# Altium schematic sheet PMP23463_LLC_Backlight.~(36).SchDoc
size 431 x 279 mm; Date: Not shown in title block; ApprovedBy: Not shown in title block; CheckedBy: Not shown in title block; Author: Not shown in title block; CompanyName: Not shown in title block; Engineer: Not shown in title block; Organization: Not shown in title block; Address1: Not shown in title block; Address2: Not shown in title block; Address3: Not shown in title block; Address4: Not shown in title block; DocumentNumber: 2; Revision: Use project parameter SCH_Rev; SheetNumber: 1; SheetTotal: 1; PageSetup: Record=PageOptions¦CenterHorizontal=True¦CenterVertical=True¦PrintScale=1.00¦XCorrection=1.00¦YCorrection=1.00¦PrintKind=0¦BorderSize=5000000¦LeftOffset=0¦BottomOffset=0¦Orientation=2¦PaperLength=1000¦PaperWidth=1000¦Scale=100¦PaperSource=15¦PrintQuality=600¦MediaType=1¦DitherType=10¦PaperKind=Letter¦PrintScaleMode=1
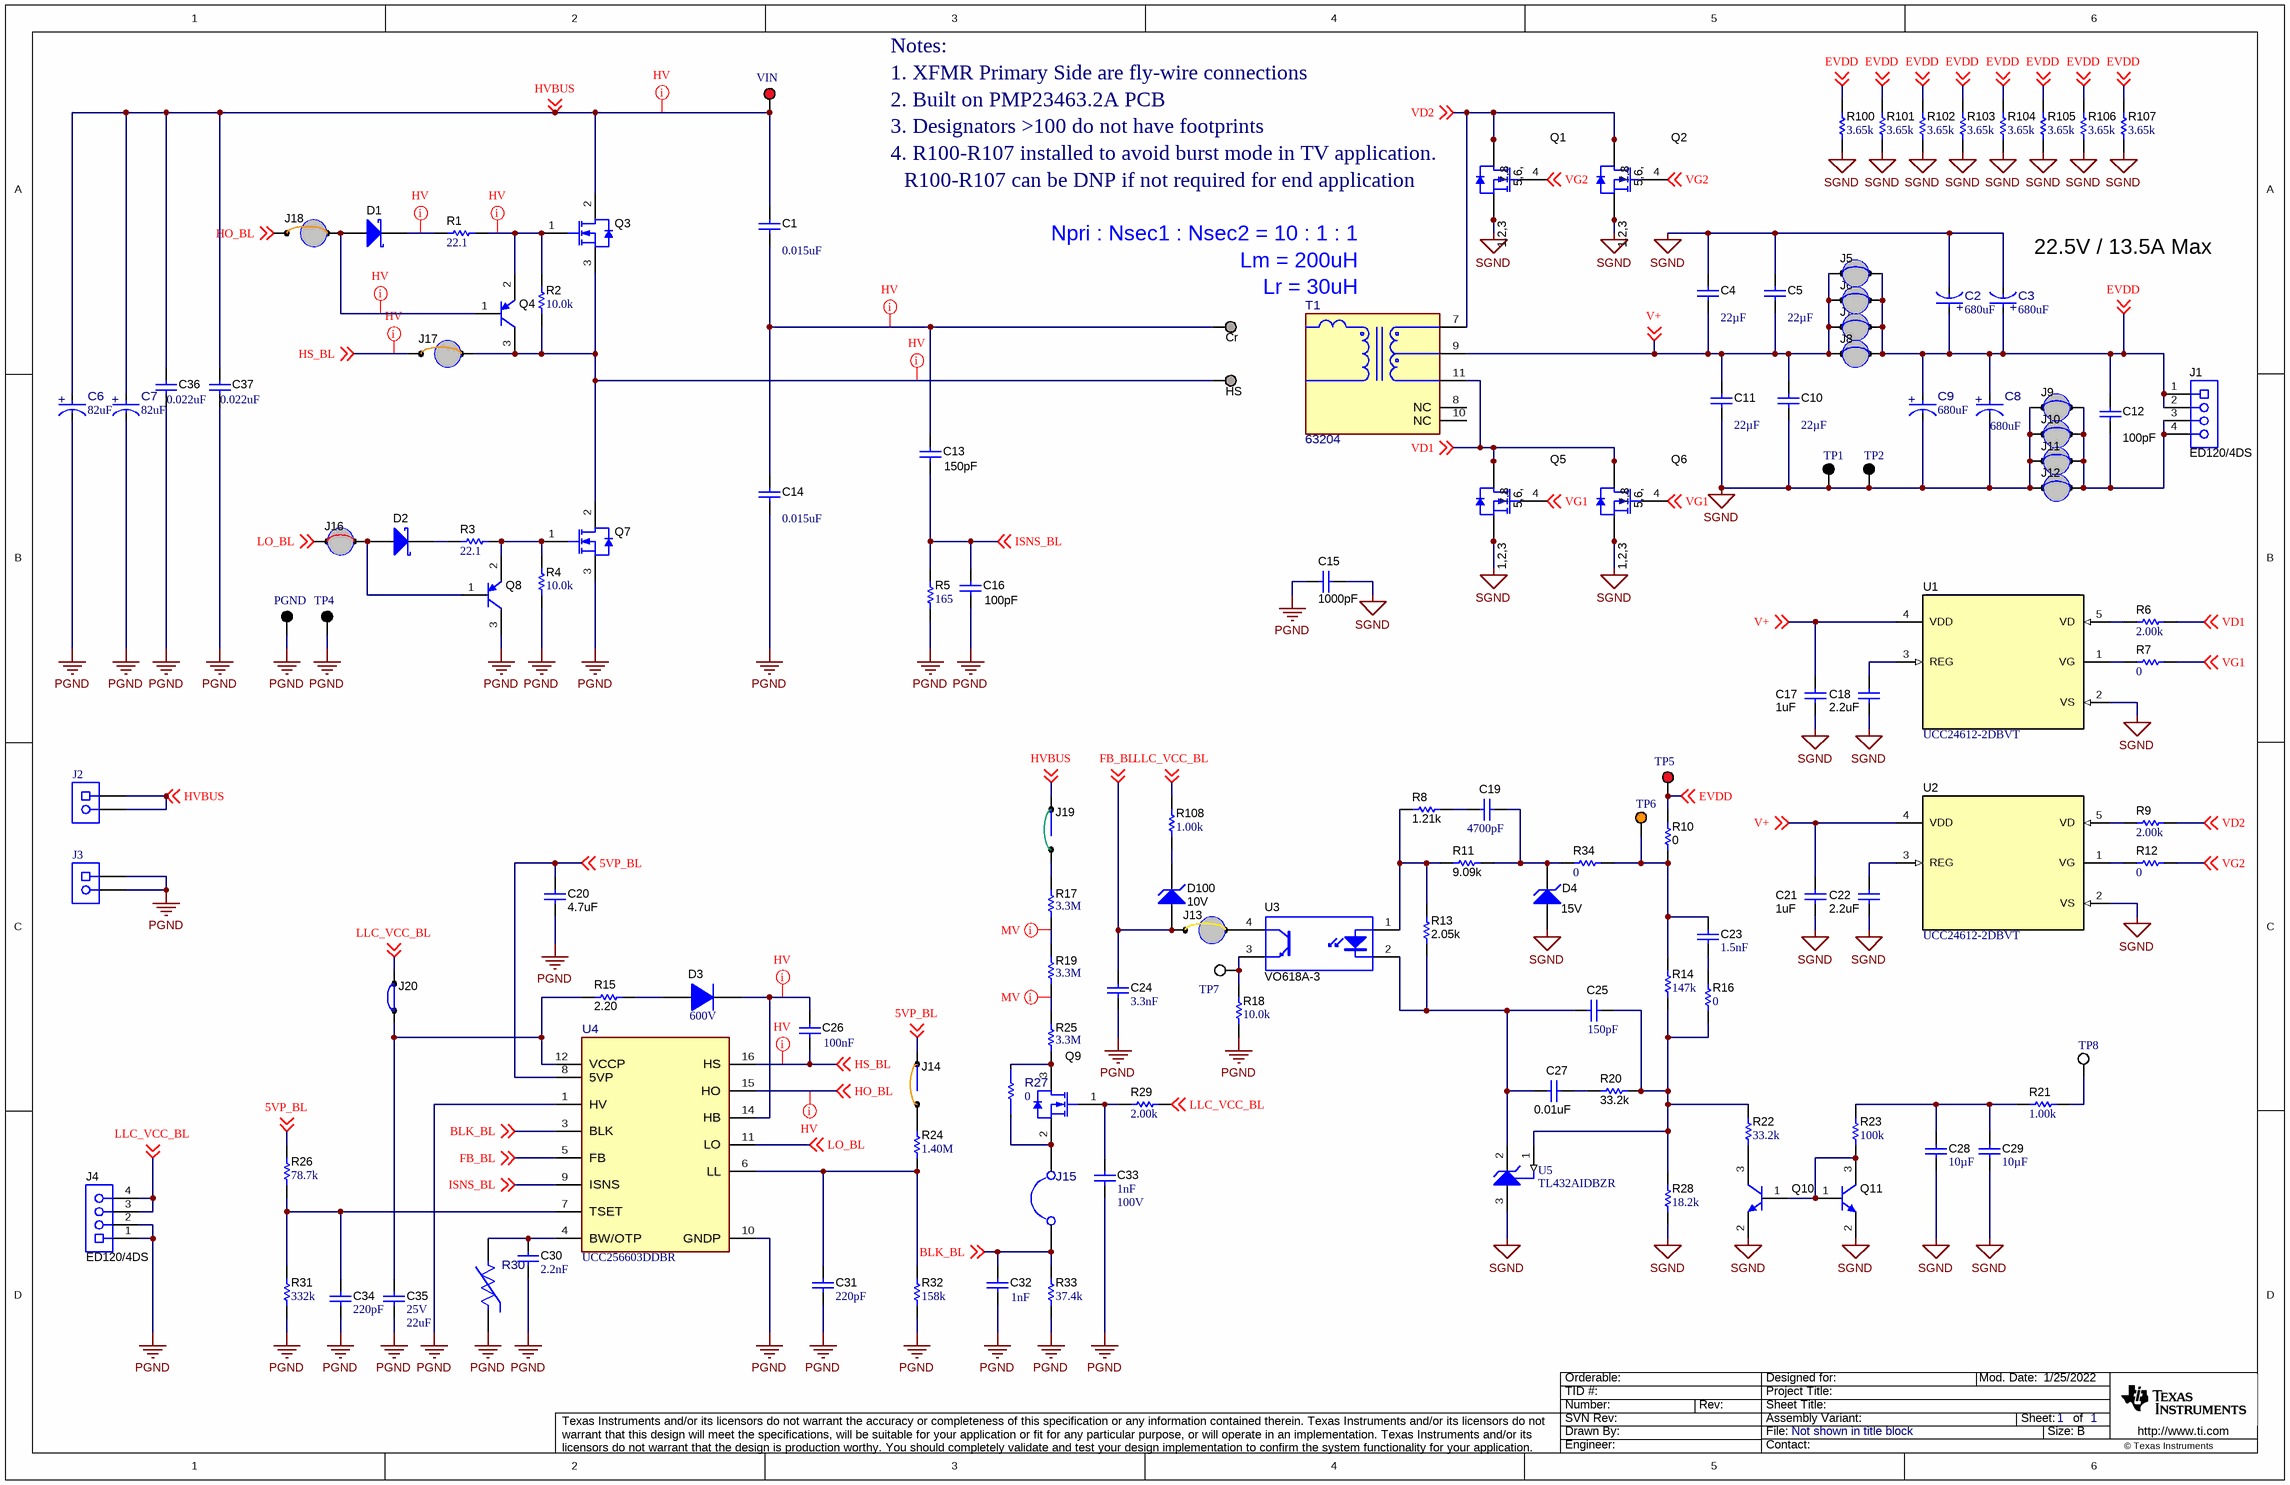
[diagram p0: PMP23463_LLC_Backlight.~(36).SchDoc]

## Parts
C1  ValueDisplayed: 0.015uF  [PHE426_1300x400x900]  (hidden comment: PHE426MA5150JR05)
C2  ValueDisplayed: 680uF  [FP-EKZM350ELL681MJ25S_horizontalUp-MFG]  (hidden comment: EKZM350ELL681MJ25S)
C3  ValueDisplayed: 680uF  [FP-EKZM350ELL681MJ25S_horizontalUp-MFG]  (hidden comment: EKZM350ELL681MJ25S)
C4  ValueDisplayed: 22µF  [1210]  (hidden comment: GMK325BJ226MM-P)
C5  ValueDisplayed: 22µF  [1210]  (hidden comment: GMK325BJ226MM-P)
C6  ValueDisplayed: 82uF  [FP-450HXW82MEFR10X60_horizontalUp]  (hidden comment: 450HXW82MEFR10X60)
C7  ValueDisplayed: 82uF  [FP-450HXW82MEFR10X60_horizontalUp]  (hidden comment: 450HXW82MEFR10X60)
C8  ValueDisplayed: 680uF  [FP-EKZM350ELL681MJ25S_horizontalUp-MFG]  (hidden comment: EKZM350ELL681MJ25S)
C9  ValueDisplayed: 680uF  [FP-EKZM350ELL681MJ25S_horizontalUp-MFG]  (hidden comment: EKZM350ELL681MJ25S)
C10  ValueDisplayed: 22µF  [1210]  (hidden comment: GMK325BJ226MM-P)
C11  ValueDisplayed: 22µF  [1210]  (hidden comment: GMK325BJ226MM-P)
C12  ValueDisplayed: 100pF  [0603L]  (hidden comment: 06035A101FAT2A)
C13  ValueDisplayed: 150pF  [1206L]  (hidden comment: GRM31A5C2J151JW01D)
C14  ValueDisplayed: 0.015uF  [PHE426_1300x400x900]  (hidden comment: PHE426MA5150JR05)
C15  ValueDisplayed: 1000pF  [CD45_700x600x1100]  (hidden comment: CD45-E2GA102M-NKA)
C16  ValueDisplayed: 100pF  [1206L]  (hidden comment: 12061A101JAT2A)
C17  ValueDisplayed: 1uF  [0603L]  (hidden comment: GRM188R71C105KE15D)
C18  ValueDisplayed: 2.2uF  [0805L]  (hidden comment: C2012X7R1V225K085AC)
C19  ValueDisplayed: 4700pF  [0603L]  (hidden comment: C0603C472J1GAC7867)
C20  ValueDisplayed: 4.7uF  [1206L]  (hidden comment: C3216X7R1E475K085AB)
C21  ValueDisplayed: 1uF  [0603L]  (hidden comment: GRM188R71C105KE15D)
C22  ValueDisplayed: 2.2uF  [0805L]  (hidden comment: C2012X7R1V225K085AC)
C23  Cap_F: 1.5nF  [0603]  (hidden comment: C0603C152K5RACTU)
C24  Cap_F: 3.3nF  [0603]  (hidden comment: C0603C332K5RACTU)
C25  ValueDisplayed: 150pF  [0603]  (hidden comment: 06035A151JAT2A)
C26  Cap_F: 100nF  [1206_180L]  (hidden comment: GRM31C5C1E104JA01L)
C27  ValueDisplayed: 0.01uF  [0603L]  (hidden comment: 06031C103JAT2A)
C28  ValueDisplayed: 10µF  [1206_180]  (hidden comment: C1206C106J3RACAUTO)
C29  ValueDisplayed: 10µF  [1206_180]  (hidden comment: C1206C106J3RACAUTO)
C30  Cap_F: 2.2nF  [0603]  (hidden comment: C0603X222K5RACTU)
C31  Cap_F: 220pF  [0603]  (hidden comment: C0603X221K5RACTU)
C32  Cap_F: 1nF  [0402L]  (hidden comment: 04025C102JAT2A)
C33  Cap_F: 1nF  VDC_V: 100V  [0603]  (hidden comment: C1608X7R2A102K080AA)
C34  Cap_F: 220pF  [0603]  (hidden comment: C0603X221K5RACTU)
C35  VDC_V: 25V  ValueDisplayed: 22uF  [1206_190]  (hidden comment: TMK316BBJ226ML-T)
C36  ValueDisplayed: 0.022uF  [1210_150]  (hidden comment: GRM32QR72J223KW01L)
C37  ValueDisplayed: 0.022uF  [1210_150]  (hidden comment: GRM32QR72J223KW01L)
Cr  0312-0-15-15-34-27-10-0  [Mill-Max_0312-0-15-15-34-27-10-0]  (value not drawn)
D1  PMEG3010EGWJ  [SOD-123]  (value not drawn)
D2  PMEG3010EGWJ  [SOD-123]  (value not drawn)
D3  Vr_V: 600V  [SMAF]  (hidden comment: ES1JAF)
D4  value 15V  [SOD-323]  (hidden comment: MM3Z15VST1G)
D100  value 10V  [SOD-523]  (hidden comment: BZT52C10T-7)
HS  0312-0-15-15-34-27-10-0  [Mill-Max_0312-0-15-15-34-27-10-0]  (value not drawn)
J1  ED120/4DS  [On-Shore_ED120_4DS]
J2  Receptacle_2x1  [On-Shore_ED120_2DS]  (value not drawn)
J3  Receptacle_2x1  [On-Shore_ED120_2DS]  (value not drawn)
J4  ED120/4DS  [On-Shore_ED120_4DS]
J5  923345-06-C  [CONN_923345-06-C]  (value not drawn)
J6  923345-06-C  [CONN_923345-06-C]  (value not drawn)
J7  923345-06-C  [CONN_923345-06-C]  (value not drawn)
J8  923345-06-C  [CONN_923345-06-C]  (value not drawn)
J9  923345-06-C  [CONN_923345-06-C]  (value not drawn)
J10  923345-06-C  [CONN_923345-06-C]  (value not drawn)
J11  923345-06-C  [CONN_923345-06-C]  (value not drawn)
J12  923345-06-C  [CONN_923345-06-C]  (value not drawn)
J13  923345-04-C  [3M_923345-04-C]  (value not drawn)
J14  923345-03-C  [923345-03-C]  (value not drawn)
J15  923345-10-C  [FP-923345-10-C_JUMPER2-MFG]  (value not drawn)
J16  923345-02-C  [923345-02-C]  (value not drawn)
J17  923345-03-C  [923345-03-C]  (value not drawn)
J18  923345-03-C  [923345-03-C]  (value not drawn)
J19  923345-05-C  [923345-05-C]  (value not drawn)
J20  923345-06-C  [CONN_923345-06-C]  (value not drawn)
PGND  5011  [Keystone5011]  (value not drawn)
Q1  BSC052N08NS5ATMA1  [PG-TDSON-8]  (value not drawn)
Q2  BSC052N08NS5ATMA1  [PG-TDSON-8]  (value not drawn)
Q3  IPP60R099C7XKSA1  [TO-220AB_Horizontal_100mil_Standoff2300]  (value not drawn)
Q4  BC858C-7-F  [SOT-23]  (value not drawn)
Q5  BSC052N08NS5ATMA1  [PG-TDSON-8]  (value not drawn)
Q6  BSC052N08NS5ATMA1  [PG-TDSON-8]  (value not drawn)
Q7  IPP60R099C7XKSA1  [TO-220AB_Horizontal_100mil_Standoff2300]  (value not drawn)
Q8  BC858C-7-F  [SOT-23]  (value not drawn)
Q9  BSS127S-7  [SOT-23]  (value not drawn)
Q10  MMBTA05LT1G  [SOT-23]  (value not drawn)
Q11  MMBTA05LT1G  [SOT-23]  (value not drawn)
R1  ValueDisplayed: 22.1  [0603]  (hidden comment: RC0603FR-0722R1L)
R2  ValueDisplayed: 10.0k  [1206]  (hidden comment: CRCW120610K0FKEA)
R3  ValueDisplayed: 22.1  [0603]  (hidden comment: RC0603FR-0722R1L)
R4  ValueDisplayed: 10.0k  [0603]  (hidden comment: M55342K12B10E0T)
R5  ValueDisplayed: 165  [1206]  (hidden comment: RC1206FR-07165RL)
R6  ValueDisplayed: 2.00k  [0603]  (hidden comment: RC0603FR-072KL)
R7  ValueDisplayed: 0  [0603L]  (hidden comment: RC0603JR-070RL)
R8  ValueDisplayed: 1.21k  [0603L]  (hidden comment: RC0603FR-071K21L)
R9  ValueDisplayed: 2.00k  [0603]  (hidden comment: RC0603FR-072KL)
R10  ValueDisplayed: 0  [0402L]  (hidden comment: RC0402JR-070RL)
R11  ValueDisplayed: 9.09k  [0603L]  (hidden comment: RC0603FR-079K09L)
R12  ValueDisplayed: 0  [0805_HV]  (hidden comment: RC0805JR-070RL)
R13  ValueDisplayed: 2.05k  [0603L]  (hidden comment: RC0603FR-072K05L)
R14  ValueDisplayed: 147k  [0603L]  (hidden comment: RC0603FR-07147KL)
R15  ValueDisplayed: 2.20  [0603L]  (hidden comment: ERJ-3RQF2R2V)
R16  ValueDisplayed: 0  [0603]  (hidden comment: RMCF0603ZT0R00)
R17  Res_ohm: 3.3M  [FP-KTR18EZPF3304_1206-MFG]  (hidden comment: KTR18EZPF3304)
R18  ValueDisplayed: 10.0k  [0402L]  (hidden comment: ERJ-2RKF1002X)
R19  Res_ohm: 3.3M  [FP-KTR18EZPF3304_1206-MFG]  (hidden comment: KTR18EZPF3304)
R20  ValueDisplayed: 33.2k  [0603L]  (hidden comment: RC0603FR-0733K2L)
R21  ValueDisplayed: 1.00k  [0603L]  (hidden comment: CRCW06031K00FKEA)
R22  ValueDisplayed: 33.2k  [0603]  (hidden comment: RC0603FR-0733K2L)
R23  ValueDisplayed: 100k  [0603]  (hidden comment: RC0603FR-07100KL)
R24  ValueDisplayed: 1.40M  [1206]  (hidden comment: RC1206FR-071M4L)
R25  Res_ohm: 3.3M  [FP-KTR18EZPF3304_1206-MFG]  (hidden comment: KTR18EZPF3304)
R26  ValueDisplayed: 78.7k  [0603]  (hidden comment: RC0603FR-0778K7L)
R27  value 0  [FP-RMCF1206ZT0R00_1206-MFG]  (hidden comment: RMCF1206ZT0R00)
R28  ValueDisplayed: 18.2k  [0603]  (hidden comment: RC0603FR-0718K2L)
R29  ValueDisplayed: 2.00k  [0603]  (hidden comment: RC0603FR-072KL)
R30  B57371V2474J060  [FP-B57371V2474J060_0603-MFG]  (value not drawn)
R31  ValueDisplayed: 332k  [0603]  (hidden comment: RC0603FR-07332KL)
R32  ValueDisplayed: 158k  [0603]  (hidden comment: RC0603FR-07158KL)
R33  ValueDisplayed: 37.4k  [0603]  (hidden comment: RC0603FR-0737K4L)
R34  ValueDisplayed: 0  [0603]  (hidden comment: RMCF0603ZT0R00)
R100  ValueDisplayed: 3.65k  [1206]  (hidden comment: RC1206FR-073K65L)
R101  ValueDisplayed: 3.65k  [1206]  (hidden comment: RC1206FR-073K65L)
R102  ValueDisplayed: 3.65k  [1206]  (hidden comment: RC1206FR-073K65L)
R103  ValueDisplayed: 3.65k  [1206]  (hidden comment: RC1206FR-073K65L)
R104  ValueDisplayed: 3.65k  [1206]  (hidden comment: RC1206FR-073K65L)
R105  ValueDisplayed: 3.65k  [1206]  (hidden comment: RC1206FR-073K65L)
R106  ValueDisplayed: 3.65k  [1206]  (hidden comment: RC1206FR-073K65L)
R107  ValueDisplayed: 3.65k  [1206]  (hidden comment: RC1206FR-073K65L)
R108  ValueDisplayed: 1.00k  [0603]  (hidden comment: ERJ-3EKF1001V)
T1  63204  [FP-63204_PTH_XRMS_80MM0_64MM0-MFG]
TP1  5011  [Keystone5011]  (value not drawn)
TP2  5011  [Keystone5011]  (value not drawn)
TP4  5011  [Keystone5011]  (value not drawn)
TP5  5010  [Keystone5010]  (value not drawn)
TP6  5013  [Keystone5013]  (value not drawn)
TP7  5012  [Keystone5012]  (value not drawn)
TP8  5012  [Keystone5012]  (value not drawn)
U1  UCC24612-2DBVT  [DBV0005A_N]
U2  UCC24612-2DBVT  [DBV0005A_N]
U3  VO618A-3  [DIP-4]
U4  UCC256603DDBR  [DDB0014A-MFG]
U5  TL432AIDBZR  [DBZ0003A_N]
VIN  5010  [Keystone5010]  (value not drawn)

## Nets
PGND: C6.1(CATHODE) C7.1(CATHODE) C14.2 C15.2 C16.2 C20.2 C24.2 C30.2 C31.2 C32.2 C33.2 C34.2 C35.2 C36.2 C37.2 J3.1 J3.2 J4.1 J4.2 PGND.1 Q7.3(S) Q8.3(C) R4.1 R5.1 R18.1 R30.1 R31.1 R32.1 R33.1 TP4.1 U4.1(HV) U4.10(GNDP)
SGND: C2.1(CATHODE) C3.1(CATHODE) C4.1 C5.1 C8.1(CATHODE) C9.1(CATHODE) C10.2 C11.2 C15.1 C17.2 C18.2 C21.2 C22.2 C28.2 C29.2 D4.2(A) J9.1 J10.1 J11.1 J12.1 Q1.1(S) Q1.2(S) Q1.3(S) Q2.1(S) Q2.2(S) Q2.3(S) Q5.1(S) Q5.2(S) Q5.3(S) Q6.1(S) Q6.2(S) Q6.3(S) Q10.2(E) Q11.2(E) R28.1 R100.1 R101.1 R102.1 R103.1 R104.1 R105.1 R106.1 R107.1 TP1.1 TP2.1 U1.2(VS) U2.2(VS) U5.3(ANODE)
5VP_BL: C20.1 J14.2 R26.2 U4.8(5VP) ; off-sheet 5VP_BL
BLK_BL: C32.1 J15.1 R33.2 U4.3(BLK) ; off-sheet BLK_BL
EVDD: C2.2(ANODE) C3.2(ANODE) C8.2(ANODE) C9.2(ANODE) C12.1 J1.1 J1.2 J5.2 J6.2 J7.2 J8.2 R10.2 R100.2 R101.2 R102.2 R103.2 R104.2 R105.2 R106.2 R107.2 TP5.1 ; off-sheet EVDD
FB_BL: C24.1 D100.2(A) J13.1 U4.5(FB) ; off-sheet FB_BL
HO_BL: J18.1 U4.15(HO) ; off-sheet HO_BL
HS_BL: C26.2 J17.1 U4.16(HS) ; off-sheet HS_BL
HVBUS: C1.1 C6.2(ANODE) C7.2(ANODE) C36.1 C37.1 J2.1 J2.2 J19.2 Q3.2(D) VIN.1 ; off-sheet HVBUS
ISNS_BL: C13.2 C16.1 R5.2 U4.9(ISNS) ; off-sheet ISNS_BL
LLC_VCC_BL: J4.3 J4.4 J20.2 R29.2 R108.2 ; off-sheet LLC_VCC_BL
LO_BL: J16.1 U4.11(LO) ; off-sheet LO_BL
V+: C4.2 C5.2 C10.1 C11.1 C17.1 C21.1 J5.1 J6.1 J7.1 J8.1 T1.9 U1.4(VDD) U2.4(VDD) ; off-sheet V+
VD1: Q5.5(D) Q5.6(D) Q5.7(D) Q5.8(D) Q5.9(D) Q6.5(D) Q6.6(D) Q6.7(D) Q6.8(D) Q6.9(D) R6.2 T1.11 ; off-sheet VD1
VD2: Q1.5(D) Q1.6(D) Q1.7(D) Q1.8(D) Q1.9(D) Q2.5(D) Q2.6(D) Q2.7(D) Q2.8(D) Q2.9(D) R9.2 T1.7 ; off-sheet VD2
VG1: Q5.4(G) Q6.4(G) R7.1 ; off-sheet VG1
VG2: Q1.4(G) Q2.4(G) R12.2 ; off-sheet VG2
NetC1_2: C1.2 C13.1 C14.1 Cr.1
NetC12_2: C12.2 J1.3 J1.4 J9.2 J10.2 J11.2 J12.2
NetC18_1: C18.1 U1.3(REG)
NetC19_1: C19.1 D4.1(K) R11.2 R34.1
NetC19_2: C19.2 R8.2
NetC22_1: C22.1 U2.3(REG)
NetC23_1: C23.1 R10.1 R14.2 R34.2 TP6.1
NetC23_2: C23.2 R16.2
NetC25_1: C25.1 R14.1 R16.1 R20.1 R22.2 R28.2 U5.1(REF)
NetC25_2: C25.2 C27.2 R13.1 U3.2(K) U5.2(CATHODE)
NetC26_1: C26.1 D3.1(K) U4.14(HB)
NetC27_1: C27.1 R20.2
NetC28_1: C28.1 C29.1 R21.1 R23.2
NetC30_1: C30.1 R30.2 U4.4(BW/OTP)
NetC31_1: C31.1 R24.1 R32.2 U4.6(LL)
NetC33_1: C33.1 Q9.1(G) R29.1
NetC34_1: C34.1 R26.1 R31.2 U4.7(TSET)
NetC35_1: C35.1 J20.1 R15.1 U4.12(VCCP)
NetD1_1: D1.1(K) R1.1
NetD1_2: D1.2(A) J18.2 Q4.1(B)
NetD2_1: D2.1(K) R3.1
NetD2_2: D2.2(A) J16.2 Q8.1(B)
NetD3_2: D3.2(A) R15.2
NetD100_1: D100.1(K) R108.1
NetHS_1: HS.1 J17.2 Q3.3(S) Q4.3(C) Q7.2(D) R2.1
NetJ13_2: J13.2 U3.4(C)
NetJ14_1: J14.1 R24.2
NetJ15_2: J15.2 Q9.2(S) R27.1
NetJ19_1: J19.1 R17.2
NetQ3_1: Q3.1(G) Q4.2(E) R1.2 R2.2
NetQ7_1: Q7.1(G) Q8.2(E) R3.2 R4.2
NetQ9_3: Q9.3(D) R25.1 R27.2
NetQ10_1: Q10.1(B) Q11.1(B) Q11.3(C) R23.1
NetQ10_3: Q10.3(C) R22.1
NetR6_1: R6.1 U1.5(VD)
NetR7_2: R7.2 U1.1(VG)
NetR8_1: R8.1 R11.1 R13.2 U3.1(A)
NetR9_1: R9.1 U2.5(VD)
NetR12_1: R12.1 U2.1(VG)
NetR17_1: R17.1 R19.2
NetR18_2: R18.2 TP7.1 U3.3(E)
NetR19_1: R19.1 R25.2
NetR21_2: R21.2 TP8.1

Not connected (* = marked no-connect by the designer): T1 8(NC) 10(NC)

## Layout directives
net class HV: HO_BL, HS_BL, HVBUS, NetC1_2, NetC26_1, NetD1_1, NetD1_2, NetHS_1, NetQ3_1
net class MV: NetR17_1, NetR19_1

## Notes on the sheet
- Notes:
- 1. XFMR Primary Side are fly-wire connections
- 2. Built on PMP23463.2A PCB
- 3. Designators >100 do not have footprints
- (near Q1) 4. R100-R107 installed to avoid burst mode in TV application.
- (near Q1) R100-R107 can be DNP if not required for end application
- Npri : Nsec1 : Nsec2 = 10 : 1 : 1
- Lm = 200uH
- (near Cr) Lr = 30uH
- (near C3) 22.5V / 13.5A Max

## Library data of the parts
C1 C14 = CMP-0012541-3: CAP, Film, 0.015 uF, 630 V, +/- 20%, TH; Manufacturer: Kemet; TaMin_C: -55°C; Polarized: N; SizeAreaWB_mm2: 90; Value1: Unknown; TaMax_C: 105°C; SizeZ_mm: 9; SizeX_mm: 13; SizeY_mm: 4; Cap_Case: 13x4x9mm; Value2: 630V; SizeArea_mm2: 52; Cap_F: 15nF; AEC Category: Q200
C2 C3 C8 C9 = CMP-0001423-2: Cap Aluminum Lytic 680uF 35V 20% (10 X 25mm) Radial 5mm 2250mA 10000h 105 Bulk; Manufacturer: United Chemi-Con; AEC Qualified: No; Cap_F: 680µF; IRMS_A: 2.25A; SizeZ_mm: 26.5mm; Dissipation Factor: 12%; Leakage Current: 238uA; Life: 10000Hours; Value: 680µF
C4 C5 C10 C11 = CMP-0085817-1: CAP, CERM, 22 µF, 35 V,+/- 20%, X5R, 1210; Manufacturer: Taiyo Yuden; Value: 22uF; VDC_V: 35V; SizeZ_mm: 1.35; TaMax_C: 85°C; U/M: EA; SizeAreaWB_mm2: 14.7; SizeX_mm: 3.2; SizeArea_mm2: 8; TaMin_C: -55°C; AEC Qualified: N; SizeY_mm: 2.5; AEC Category: Q200
C6 C7 = CMP-0120349-2: 82 µF 450 V Aluminum Electrolytic Capacitors Radial, Can 2000 Hrs @ 105°C; Manufacturer: Rubycon; AEC Qualified: No; Cap_F: 82µF; IRMS_A: 710mA; SizeZ_mm: 62mm; Tolerance_%: 20%; VDC_V: 450V; Dissipation Factor: 25%; Leakage Current: 576.28uA; Life: 2000Hours; Value: 82µF
C12 = CMP-0006762-4: CAP, CERM, 100 pF, 50 V, +/- 1%, C0G/NP0, 0603; Manufacturer: AVX; TaMin_C: -55°C; Polarized: N; SizeAreaWB_mm2: 4.68; Value1: Unknown; U/M: EA; TaMax_C: 125°C; SizeZ_mm: 1; SizeX_mm: 1.6; SizeY_mm: 0.8; Cap_Case: 0603; Value2: 50V; SizeArea_mm2: 1.28; CompType: Capacitor; Value: 100pF; AEC Category: Q200
C13 = CMP-0008885-2: CAP, CERM, 150 pF, 630 V, +/- 5%, C0G/NP0, 1206; Manufacturer: MuRata; TaMin_C: -55°C; Polarized: N; SizeAreaWB_mm2: 10.92; Value1: Unknown; U/M: EA; Value: 150pF; TaMax_C: 125°C; SizeZ_mm: 1.35; SizeX_mm: 3.2; SizeY_mm: 1.6; Cap_Case: 1206; Value2: 630V; SizeArea_mm2: 5.12; CompType: Capacitor; AEC Category: Q200
C15 = CMP-0009595-2: CAP, CERM, 1000 pF,  V, +/- 20%, E, D7xT6mm; Manufacturer: TDK; TaMin_C: -25°C; Polarized: N; SizeAreaWB_mm2: 101.2; Value1: Unknown; U/M: EA; Value: 1000pF; TaMax_C: 125°C; SizeZ_mm: 11; SizeX_mm: 10.65; SizeY_mm: 6; Cap_Case: 7x6x11mm; SizeArea_mm2: 63.9; Cap_F: 1nF; AEC Category: Q200
C16 = CMP-0008462-2: CAP, CERM, 100 pF, 100 V, +/- 5%, C0G/NP0, 1206; Manufacturer: AVX; TaMin_C: -55°C; ESR_ohm: 7.01d; Polarized: N; SizeAreaWB_mm2: 10.92; Value1: 0.701 ohm; U/M: EA; Value: 100pF; TaMax_C: 125°C; SizeZ_mm: 1.35; SizeX_mm: 3.2; SizeY_mm: 1.6; Cap_Case: 1206; Value2: 100V; SizeArea_mm2: 5.12; CompType: Capacitor; AEC Category: Q200
C17 C21 = CMP-0007380-4: CAP, CERM, 1 uF, 16 V, +/- 10%, X7R, 0603; Manufacturer: MuRata; TaMin_C: -55°C; Polarized: N; SizeAreaWB_mm2: 4.68; Value1: Unknown; U/M: EA; Value: 1uF; TaMax_C: 125°C; SizeZ_mm: 1; SizeX_mm: 1.6; SizeY_mm: 0.8; Cap_Case: 0603; Value2: 16V; SizeArea_mm2: 1.28; CompType: Capacitor; Cap_F: 1µF; AEC Category: Q200
C18 C22 = CMP-0007883-2: CAP, CERM, 2.2 uF, 35 V, +/- 10%, X7R, 0805; Manufacturer: TDK; TaMin_C: -55°C; Polarized: N; SizeAreaWB_mm2: 6.75; Value1: Unknown; U/M: EA; Value: 2.2uF; TaMax_C: 125°C; SizeZ_mm: 1.45; SizeX_mm: 2; SizeY_mm: 1.25; Cap_Case: 0805; Value2: 35V; SizeArea_mm2: 2.5; CompType: Capacitor; Cap_F: 2.2µF; AEC Category: Q200
C19 = CMP-0006941-4: CAP, CERM, 4700 pF, 100 V, +/- 5%, C0G/NP0, 0603; Manufacturer: Kemet; TaMin_C: -55°C; Polarized: N; SizeAreaWB_mm2: 4.68; Value1: Unknown; U/M: EA; Value: 4700pF; TaMax_C: 125°C; SizeZ_mm: 1; SizeX_mm: 1.6; SizeY_mm: 0.8; Cap_Case: 0603; Value2: 100V; SizeArea_mm2: 1.28; Cap_F: 4.7nF; AEC Category: Q200
C20 = CMP-0008693-2: CAP, CERM, 4.7 uF, 25 V, +/- 10%, X7R, 1206; Manufacturer: TDK; TaMin_C: -55°C; Polarized: N; SizeAreaWB_mm2: 10.92; Value1: Unknown; U/M: EA; Value: 4.7uF; TaMax_C: 125°C; SizeZ_mm: 1.35; SizeX_mm: 3.2; SizeY_mm: 1.6; Cap_Case: 1206; Value2: 25V; SizeArea_mm2: 5.12; CompType: Capacitor; Cap_F: 4.7µF; AEC Category: Q200
C23 = CMP-0006881-4: CAP, CERM, 1500 pF, 50 V, +/- 10%, X7R, 0603; Manufacturer: Kemet; TaMin_C: -55°C; Polarized: N; SizeAreaWB_mm2: 4.68; Value1: Unknown; U/M: EA; Value: 1500pF; TaMax_C: 125°C; SizeZ_mm: 1; SizeX_mm: 1.6; SizeY_mm: 0.8; Value2: 50V; SizeArea_mm2: 1.28; AEC Category: Q200
C24 = CMP-0006922-4: CAP, CERM, 3300 pF, 50 V, +/- 10%, X7R, 0603; Manufacturer: Kemet; TaMin_C: -55°C; Polarized: N; SizeAreaWB_mm2: 4.68; Value1: Unknown; U/M: EA; Value: 3300pF; TaMax_C: 125°C; SizeZ_mm: 1; SizeX_mm: 1.6; SizeY_mm: 0.8; Value2: 50V; SizeArea_mm2: 1.28; AEC Category: Q200
C25 = CMP-0006768-4: CAP, CERM, 150 pF, 50 V, +/- 5%, C0G/NP0, 0603; Manufacturer: AVX; TaMin_C: -55°C; ESR_ohm: 0.098; Polarized: N; SizeAreaWB_mm2: 4.68; Value1: 0.098 ohm; U/M: EA; Value: 150pF; TaMax_C: 125°C; SizeZ_mm: 1; SizeX_mm: 1.6; SizeY_mm: 0.8; Value2: 50V; SizeArea_mm2: 1.28; AEC Category: Q200
C26 = CMP-0064950-2: CAP, CERM, 0.1 uF, 25 V,+/- 5%, C0G/NP0, 1206; Manufacturer: MuRata; TaMin_C: -55°C; Polarized: N; SizeAreaWB_mm2: 10.92; Value1: Unknown; U/M: EA; Value: 0.1uF; TaMax_C: 125°C; SizeZ_mm: 1.8; SizeX_mm: 3.2; SizeY_mm: 1.6; Cap_Case: 1206; Value2: 25V; SizeArea_mm2: 5.12; AEC Category: Q200
C27 = CMP-0006726-4: CAP, CERM, 0.01 uF, 100 V, +/- 5%, X7R, 0603; Manufacturer: AVX; TaMin_C: -55°C; ESR_ohm: 0.098; Polarized: N; SizeAreaWB_mm2: 4.68; Value1: 0.098 ohm; U/M: EA; Value: 0.01uF; TaMax_C: 125°C; SizeZ_mm: 1; SizeX_mm: 1.6; SizeY_mm: 0.8; Cap_Case: 0603; Value2: 100V; SizeArea_mm2: 1.28; Cap_F: 10nF; AEC Category: Q200
C28 C29 = CMP-0081062-1: CAP, CERM, 10 µF, 25 V,+/- 5%, X7R, AEC-Q200 Grade 1, 1206; Manufacturer: Kemet; TaMin_C: -55°C; Polarized: N; SizeAreaWB_mm2: 10.92; U/M: EA; Value: 10uF; TaMax_C: 125°C; SizeZ_mm: 1.8; SizeX_mm: 3.2; SizeY_mm: 1.6; Value2: 25V; SizeArea_mm2: 5.12; AEC Qualified: Y; AEC Grade: 1; AEC Category: Q200
C30 = CMP-0006983-4: CAP, CERM, 2200 pF, 50 V, +/- 10%, X7R, 0603; Manufacturer: Kemet; TaMin_C: -55°C; Polarized: N; SizeAreaWB_mm2: 4.68; Value1: Unknown; U/M: EA; Value: 2200pF; TaMax_C: 125°C; SizeZ_mm: 1; SizeX_mm: 1.6; SizeY_mm: 0.8; Value2: 50V; SizeArea_mm2: 1.28; AEC Category: Q200
C31 C34 = CMP-0006982-4: CAP, CERM, 220 pF, 50 V, +/- 10%, X7R, 0603; Manufacturer: Kemet; TaMin_C: -55°C; Polarized: N; SizeAreaWB_mm2: 4.68; Value1: Unknown; U/M: EA; Value: 220pF; TaMax_C: 125°C; SizeZ_mm: 1; SizeX_mm: 1.6; SizeY_mm: 0.8; Value2: 50V; SizeArea_mm2: 1.28; AEC Category: Q200
C32 = CMP-0861060-1: CAP, CERM, 1000 pF, 50 V,+/- 5%, X7R, 0402; Manufacturer: AVX; Value2: 50V; SizeY_mm: 0.5; AEC Category: Q200; Polarized: N; Green_Lifecycle: Active; SizeAreaWB_mm2: 3; ValueDisplayed: 1000pF; Cap_Case: 0402; Value: 1000pF; TaMin_C: -55°C; U/M: EA; Green_REACh: Passed; SizeZ_mm: 0.6; SizeX_mm: 1; TaMax_C: 125°C
C33 = CMP-0007053-4: CAP, CERM, 1000 pF, 100 V, +/- 10%, X7R, 0603; Manufacturer: TDK; TaMin_C: -55°C; Polarized: N; SizeAreaWB_mm2: 4.68; Value1: Unknown; U/M: EA; Value: 1000pF; TaMax_C: 125°C; SizeZ_mm: 1; SizeX_mm: 1.6; SizeY_mm: 0.8; SizeArea_mm2: 1.28; AEC Category: Q200
C35 = CMP-0009024-2: CAP, CERM, 22 uF, 25 V, +/- 20%, X5R, 1206_190; Manufacturer: Taiyo Yuden; TaMin_C: -55°C; Polarized: N; SizeAreaWB_mm2: 10.92; Value1: Unknown; U/M: EA; Value: 22uF; TaMax_C: 85°C; SizeZ_mm: 1.9; SizeX_mm: 3.2; SizeY_mm: 1.6; Cap_Case: 1206; SizeArea_mm2: 5.12; Cap_F: 22µF; AEC Category: Q200
C36 C37 = CMP-0009248-2: CAP, CERM, 0.022 uF, 630 V, +/- 10%, X7R, 1210; Manufacturer: MuRata; TaMin_C: -55°C; Polarized: N; SizeAreaWB_mm2: 14.7; Value1: Unknown; U/M: EA; TaMax_C: 125°C; SizeZ_mm: 1.5; SizeX_mm: 3.2; SizeY_mm: 2.5; Cap_Case: 1210; Value2: 630V; SizeArea_mm2: 8; Cap_F: 22nF; AEC Category: Q200
Cr HS = CMP-0055026-1: Pin Receptacle, .032-.046" .075" Dia, Gold, TH; Manufacturer: Mill-Max; CNHeader: FALSE; Green_Lifecycle: Active; Gender: Female; Green_REACh: Passed
D1 D2 = CMP-0079240-2: Diode, Schottky, 30 V, 1 A, AEC-Q101, SOD-123; Manufacturer: Nexperia; SizeZ_mm: 1.35; Value: 30V; Value1: 1A; AEC Category: Q101; Vf_V: 560mV; SizeX_mm: 3.85; SizeAreaWB_mm2: 13.095; Value2: 0.56V; SizeY_mm: 1.7; AEC Qualified: Y; TJmax_C: 150°C; SizeArea_mm2: 6.545
D3 = CMP-0029162-2: Diode, Ultrafast, 600 V, 1 A, AEC-Q101, SMAF; Manufacturer: Fairchild Semiconductor; Io_A: 1A; Green_Lifecycle: Not Set; SizeAreaWB_mm2: 19.95; Green_REACh: Incomplete; TJmax_C: 150°C; Value: 600V; SizeZ_mm: 1; SizeX_mm: 4.7; SizeY_mm: 2.5; Vf_V: 1.7V; SizeArea_mm2: 11.75; AEC Qualified: Y; AEC Category: Q101
D4 = CMP-0085762-1: Diode, Zener, 15 V, 300 mW, SOD-323; Manufacturer: ON Semiconductor; Value1: 0.3W; Power_W: 300mW; AEC Category: Q101; SizeX_mm: 2.7; SizeArea_mm2: 3.645; SizeAreaWB_mm2: 8.695; SizeY_mm: 1.35; AEC Qualified: N; RJA_CperW: 416; SizeZ_mm: 1
D100 = CMP-0005875-5: Diode, Zener, 10 V, 300 mW, SOD-523; Manufacturer: Diodes Inc.; RJA_CperW: 417; Power_W: 300mW; SizeZ_mm: 0.65; SizeY_mm: 0.9; SizeAreaWB_mm2: 5.13; Value1: 0.3W; SizeArea_mm2: 1.53; SizeX_mm: 1.7; AEC Category: Q101
J1 J4 = CMP-0074939-1: Terminal Block, 5.08 mm, 4x1, Brass, TH; Manufacturer: On-Shore Technology; Cert_VDE: Y; CNHeader: False; Current_A: 15A; Green_Lifecycle: Not Set; Shrouded: N; Gender: Female; Green_REACh: Incomplete; Voltage_V: 300V; Row_Count: 1; Pitch_mm: 5.08; CT: True
J2 J3 = CMP-0074910-1: Terminal Block, 5.08 mm, 2x1, Brass, TH; PartNumber: ED120/2DS; Manufacturer: On-Shore Technology; Pitch_mm: 5.08; Gender: Female; Shrouded: N; Row_Count: 1; Current_A: 15A; Voltage_V: 300V; Cert_CULUS: Y; Green_Lifecycle: Not Set; Green_REACh: Incomplete; CNHeader: False; CT: True
J5-J12 J20 = CMP-0074937-1: Jumper Wire, 600mil spacing, Blue, pkg of 150, TH; Manufacturer: 3M; CNHeader: False; Green_Lifecycle: Active; Green_REACh: Passed
J13 = CMP-0075057-1: Jumper Wire, 400 mil Spacing, Yellow, Pkg of 200; Manufacturer: 3M; CNHeader: False; Green_Lifecycle: Active; Green_REACh: Passed
J14 J17 J18 = CMP-0055440-1: Jumper Wire, 300mil spacing, Orange, pkg of 200; Manufacturer: 3M; CNHeader: FALSE; Green_Lifecycle: Active; Green_REACh: Passed
J15 = CMP-0086742-1: Jumper Wire Pre-Formed for Breadboard 1.000" (25.40mm) 22 AWG 100 per Pkg; Manufacturer: 3M
J16 = CMP-0055439-1: Jumper Wire, 200mil spacing, Red, pkg of 200; Manufacturer: 3M; CNHeader: FALSE; Green_Lifecycle: Active; Green_REACh: Passed
J19 = CMP-0055441-1: Jumper Wire, 500mil spacing, Green, pkg of 200; Manufacturer: 3M; CNHeader: FALSE; Green_Lifecycle: Active; Green_REACh: Passed
PGND TP4 = CMP-0055148-2: Test Point, Multipurpose, Black, TH; Manufacturer: Keystone Electronics; CNHeader: FALSE; Green_Lifecycle: Active; Green_REACh: Passed; ContactFinish: Silver; CT: TRUE
Q1 Q2 Q5 Q6 = CMP-0078881-1: MOSFET, N-CH, 80 V, 95 A, PG-TDSON-8; Manufacturer: Infineon Technologies; Alternate Manufacturer: None; ChType: N; QgTyp_nC: 32; SizeAreaWB_mm2: 55.131; SizeArea_mm2: 29.351; IdsMax_A: 95A; VdsMax_V: 80V; Vgs_V: 20V; AEC Category: Q101; Value: 80V; SizeZ_mm: 1.12; SizeY_mm: 4.9; Value2: 32 nC; U/M: EA; Value1: ? ohm; SizeX_mm: 5.99
Q3 Q7 = CMP-0001171-3: MOSFET, N-CH, 600 V, 22 A, TO-220AB; Alternate Manufacturer: None; Manufacturer: Infineon Technologies; SizeZ_mm: 19.4; ChType: N; Value2: 42 nC; VdsMax_V: 600V; SizeX_mm: 10.2; SizeY_mm: 4.5; Vgs_V: 30V; QgTyp_nC: 42; Value: 600V; SizeArea_mm2: 45.9; AEC Category: Q101; IdsMax_A: 22A; SizeAreaWB_mm2: 79.3; U/M: EA
Q4 Q8 = CMP-0000317-2: Transistor, PNP, 30 V, 0.1 A, SOT-23; Manufacturer: Diodes Inc.; TaMax_C: 150°C; Value2: 600; Value1: 0.1 A; Vcesat1_V: 75mV; SizeX_mm: 2.5; SizeY_mm: 3; TaMin_C: -65°C; IcRated_A: 1dA; CompType: BJT; SizeZ_mm: 1.1; Value: 30 V; SizeArea_mm2: 7.5; NPN: 0; Vceo_V: 30V; PNP: 1; AEC Category: Q101; SizeAreaWB_mm2: 14; U/M: EA
Q9 = CMP-0001149-3: MOSFET, N-CH, 600 V, 0.05 A, SOT-23; Alternate Manufacturer: None; Manufacturer: Diodes Inc.; SizeZ_mm: 1.1; ChType: N; Value2: 1.08 nC; VdsMax_V: 600V; SizeX_mm: 2.5; SizeY_mm: 3; Vgs_V: 20V; QgTyp_nC: 1.08; Value: 600V; SizeArea_mm2: 7.5; AEC Category: Q101; IdsMax_A: 50mA; SizeAreaWB_mm2: 14; U/M: EA
Q10 Q11 = CMP-0000488-2: Transistor, NPN, 60 V, 0.5 A, AEC-Q101, SOT-23; Manufacturer: ON Semiconductor; TaMax_C: 150°C; Value1: 0.5 A; Vcesat1_V: 2.5dV; SizeX_mm: 2.5; SizeY_mm: 3; TaMin_C: -55°C; IcRated_A: 5dA; CompType: BJT; SizeZ_mm: 1.1; AEC Qualified: Y; Value: 60 V; SizeArea_mm2: 7.5; NPN: 1; Vceo_V: 60V; PNP: 0; AEC Category: Q101; SizeAreaWB_mm2: 14; U/M: EA
R1 R3 = CMP-0022926-4: RES, 22.1, 1%, 0.1 W, 0603; Manufacturer: Yageo; Power_W: 100mW; TempCo: 100 ppm/C; Value_Code: 22R1; Value: 22.1; EIA_Code: E96; SizeX_mm: 1.6; SizeY_mm: 0.8; SizeZ_mm: 1; Value2: 0.1W; SizeArea_mm2: 1.28; AEC Qualified: N; VDC_V: 75V; AEC Category: Q200; SizeAreaWB_mm2: 4.68
R2 = CMP-0016577-3: RES, 10.0 k, 1%, 0.25 W, AEC-Q200 Grade 0, 1206; Manufacturer: Vishay-Dale; Power_W: 250mW; TempCo: 100 ppm/C; Value_Code: 10k0; Value: 10.0k; EIA_Code: E96; Res_ohm: 10k; SizeX_mm: 3.2; SizeY_mm: 1.6; SizeZ_mm: 1.35; Value2: 0.25W; SizeArea_mm2: 5.12; AEC Qualified: Y; VDC_V: 200V; AEC Category: Q200; AEC Grade: 0
R4 = CMP-0080488-1: RES, 10.0 k, 1%, 0.1 W, 0603; Manufacturer: TT Electronics/IRC; Power_W: 100mW; TempCo: 100 ppm/C; SizeAreaWB_mm2: 4.68; Value_Code: 10k0; Value: 10.0k; EIA_Code: E96; Res_ohm: 10k; SizeX_mm: 1.6; SizeY_mm: 0.8; SizeZ_mm: 1; Value2: 0.1W; SizeArea_mm2: 1.28; AEC Qualified: N; AEC Category: Q200
R5 = CMP-0017925-2: RES, 165, 1%, 0.25 W, 1206; Manufacturer: Yageo America; Power_W: 250mW; TempCo: 100 ppm/C; Value_Code: 165R; U/M: EA; Value: 165; EIA_Code: E96; SizeX_mm: 3.2; SizeY_mm: 1.6; SizeZ_mm: 1.35; Value2: 0.25W; SizeArea_mm2: 5.12; VDC_V: 200V; AEC Category: Q200
R6 R9 R29 = CMP-0023000-5: RES, 2.00 k, 1%, 0.1 W, 0603; Manufacturer: Yageo; Power_W: 100mW; TempCo: 100 ppm/C; Value_Code: 2k00; Value: 2.00k; EIA_Code: E96; Res_ohm: 2k; SizeX_mm: 1.6; SizeY_mm: 0.8; SizeZ_mm: 1; Value2: 0.1W; SizeArea_mm2: 1.28; AEC Qualified: N; VDC_V: 75V; AEC Category: Q200; SizeAreaWB_mm2: 4.68
R7 = CMP-0025885-5: RES, 0, 5%, 0.1 W, 0603; Manufacturer: Yageo; Power_W: 100mW; TempCo: 200 ppm/C; Value_Code: 0000; Value: 0; EIA_Code: E24; SizeX_mm: 1.6; SizeZ_mm: 1; Value2: 0.1W; SizeArea_mm2: 1.28; AEC Qualified: N; VDC_V: 75V; AEC Category: Q200; SizeY_mm: 0.8; SizeAreaWB_mm2: 4.68
R8 = CMP-0022871-5: RES, 1.21 k, 1%, 0.1 W, 0603; Manufacturer: Yageo; Power_W: 100mW; TempCo: 100 ppm/C; Value_Code: 1k21; Value: 1.21k; EIA_Code: E96; SizeX_mm: 1.6; SizeY_mm: 0.8; SizeZ_mm: 1; Value2: 0.1W; SizeArea_mm2: 1.28; AEC Qualified: N; VDC_V: 75V; AEC Category: Q200; SizeAreaWB_mm2: 4.68
R10 = CMP-0027004-2: RES, 0, 5%, 0.063 W, 0402; Manufacturer: Yageo America; Power_W: 63mW; TempCo: 200 ppm/C; Value_Code: 0000; U/M: EA; Value: 0; EIA_Code: E24; SizeX_mm: 1; SizeY_mm: 0.5; SizeZ_mm: 0.6; Value2: 0.063W; CompType: Resistor; VDC_V: 50V; AEC Category: Q200
R11 = CMP-0023332-5: RES, 9.09 k, 1%, 0.1 W, 0603; Manufacturer: Yageo; Power_W: 100mW; TempCo: 100 ppm/C; Value_Code: 9k09; Value: 9.09k; EIA_Code: E96; SizeX_mm: 1.6; SizeY_mm: 0.8; SizeZ_mm: 1; Value2: 0.1W; SizeArea_mm2: 1.28; AEC Qualified: N; VDC_V: 75V; AEC Category: Q200; SizeAreaWB_mm2: 4.68
R12 = CMP-0020803-2: RES, 0, 5%, 0.125 W, 0805; Manufacturer: Yageo America; Power_W: 125mW; TempCo: 200 ppm/C; Value_Code: 0000; U/M: EA; Value: 0; EIA_Code: E24; SizeX_mm: 2; SizeY_mm: 1.25; SizeZ_mm: 1.45; Value2: 0.125W; SizeArea_mm2: 2.5; VDC_V: 150V; AEC Category: Q200
R13 = CMP-0022981-5: RES, 2.05 k, 1%, 0.1 W, 0603; Manufacturer: Yageo; Power_W: 100mW; TempCo: 100 ppm/C; Value_Code: 2k05; Value: 2.05k; EIA_Code: E96; SizeX_mm: 1.6; SizeY_mm: 0.8; SizeZ_mm: 1; Value2: 0.1W; SizeArea_mm2: 1.28; AEC Qualified: N; VDC_V: 75V; AEC Category: Q200; SizeAreaWB_mm2: 4.68
R14 = CMP-0022800-4: RES, 147 k, 1%, 0.1 W, 0603; Manufacturer: Yageo; Power_W: 100mW; TempCo: 100 ppm/C; Value: 147k; EIA_Code: E96; SizeX_mm: 1.6; SizeY_mm: 0.8; SizeZ_mm: 1; Value2: 0.1W; SizeArea_mm2: 1.28; AEC Qualified: N; VDC_V: 75V; AEC Category: Q200; SizeAreaWB_mm2: 4.68
R15 = CMP-0022711-2: RES, 2.20, 1%, 0.1 W, 0603; Manufacturer: Panasonic; Power_W: 100mW; TempCo: 200 ppm/C; Value_Code: 2R20; U/M: EA; Value: 2.20; Res_ohm: 2.2; SizeX_mm: 1.6; SizeY_mm: 0.8; SizeZ_mm: 1; Value2: 0.1W; SizeArea_mm2: 1.28; CompType: Resistor; AEC Category: Q200
R16 R34 = CMP-0023343-3: RES, 0, 1%, 0.1 W, AEC-Q200 Grade 0, 0603; Manufacturer: Stackpole Electronics Inc; Power_W: 100mW; TempCo: ppm/C; U/M: EA; Value: 0; SizeX_mm: 1.6; SizeY_mm: 0.8; SizeZ_mm: 1; Value2: 0.1W; SizeArea_mm2: 1.28; AEC Qualified: Y; AEC Category: Q200
R17 R19 R25 = CMP-0087456-2: 3.3 MOhms ±1% 0.25W, 1/4W Chip Resistor 1206 (3216 Metric) Automotive AEC-Q200, High Voltage Thick Film; Manufacturer: Rohm Semiconductor; AEC Qualified: Yes; Power_W: 250mW; SizeZ_mm: 0.65mm; AEC Grade: Grade 0; TempCo: 100ppm/°C; VDC_V: 500V
R18 = CMP-0026658-1: RES, 10.0 k, 1%, 0.1 W, 0402; Manufacturer: Panasonic; Power_W: 100mW; TempCo: 100 ppm/C; Value_Code: 10k0; U/M: EA; Value: 10.0k; EIA_Code: E96; Res_ohm: 10k; SizeX_mm: 1; SizeY_mm: 0.5; SizeZ_mm: 0.6; Value2: 0.1W; VDC_V: 50V; AEC Category: Q200
R20 R22 = CMP-0023036-5: RES, 33.2 k, 1%, 0.1 W, 0603; Manufacturer: Yageo; Power_W: 100mW; TempCo: 100 ppm/C; Value_Code: 33k2; Value: 33.2k; EIA_Code: E96; SizeX_mm: 1.6; SizeY_mm: 0.8; SizeZ_mm: 1; Value2: 0.1W; SizeArea_mm2: 1.28; AEC Qualified: N; VDC_V: 75V; AEC Category: Q200; SizeAreaWB_mm2: 4.68
R21 = CMP-0022109-5: RES, 1.00 k, 1%, 0.1 W, AEC-Q200 Grade 0, 0603; Manufacturer: Vishay-Dale; Power_W: 100mW; TempCo: 100 ppm/C; Value_Code: 1k00; Value: 1.00k; EIA_Code: E96; Res_ohm: 1k; SizeX_mm: 1.6; SizeY_mm: 0.8; SizeZ_mm: 1; Value2: 0.1W; SizeArea_mm2: 1.28; AEC Qualified: Y; VDC_V: 75V; AEC Category: Q200; AEC Grade: 0
R23 = CMP-0022735-5: RES, 100 k, 1%, 0.1 W, 0603; Manufacturer: Yageo; Power_W: 100mW; TempCo: 100 ppm/C; Value: 100k; EIA_Code: E96; SizeX_mm: 1.6; SizeY_mm: 0.8; SizeZ_mm: 1; Value2: 0.1W; SizeArea_mm2: 1.28; AEC Qualified: N; VDC_V: 75V; AEC Category: Q200; SizeAreaWB_mm2: 4.68
R24 = CMP-0018012-2: RES, 1.40 M, 1%, 0.25 W, 1206; Manufacturer: Yageo America; Power_W: 250mW; TempCo: 100 ppm/C; Value_Code: 1M40; U/M: EA; Value: 1.40Meg; EIA_Code: E96; Res_ohm: 1.4M; SizeX_mm: 3.2; SizeY_mm: 1.6; SizeZ_mm: 1.35; Value2: 0.25W; SizeArea_mm2: 5.12; VDC_V: 200V; AEC Category: Q200
R26 = CMP-0023275-5: RES, 78.7 k, 1%, 0.1 W, 0603; Manufacturer: Yageo; Power_W: 100mW; TempCo: 100 ppm/C; Value_Code: 78k7; Value: 78.7k; EIA_Code: E96; SizeX_mm: 1.6; SizeY_mm: 0.8; SizeZ_mm: 1; Value2: 0.1W; SizeArea_mm2: 1.28; AEC Qualified: N; VDC_V: 75V; AEC Category: Q200; SizeAreaWB_mm2: 4.68
R27 = CMP-0093609-1: 0Ω ±0 0.25W 1206 Thick Film Chip Resistor AEC-Q200 compliant; Manufacturer: Stackpole Electronics; AEC Qualified: Yes; VDC_V: 200V; AEC Grade: Grade 0; Power_W: 250mW; SizeZ_mm: 0.7mm
R28 = CMP-0022850-5: RES, 18.2 k, 1%, 0.1 W, 0603; Manufacturer: Yageo; Power_W: 100mW; TempCo: 100 ppm/C; Value_Code: 18k2; Value: 18.2k; EIA_Code: E96; SizeX_mm: 1.6; SizeY_mm: 0.8; SizeZ_mm: 1; Value2: 0.1W; SizeArea_mm2: 1.28; AEC Qualified: N; VDC_V: 75V; AEC Category: Q200; SizeAreaWB_mm2: 4.68
R30 = CMP-0096703-1: NTC Thermistor 470k 0603 (1608 Metric); Manufacturer: TDK; AEC Qualified: No; Res_ohm: 470kΩ; Power_W: 180mW; B 25 50: 4386K; B 25 100: 4480K; SizeZ_mm: 0.9mm; B 25 85: 4455K; B Tolerance: 3%; Tolerance_%: 5%
R31 = CMP-0023034-4: RES, 332 k, 1%, 0.1 W, 0603; Manufacturer: Yageo; Power_W: 100mW; TempCo: 100 ppm/C; Value: 332k; EIA_Code: E96; SizeX_mm: 1.6; SizeY_mm: 0.8; SizeZ_mm: 1; Value2: 0.1W; SizeArea_mm2: 1.28; AEC Qualified: N; VDC_V: 75V; AEC Category: Q200; SizeAreaWB_mm2: 4.68
R32 = CMP-0022812-4: RES, 158 k, 1%, 0.1 W, 0603; Manufacturer: Yageo; Power_W: 100mW; TempCo: 100 ppm/C; Value: 158k; EIA_Code: E96; SizeX_mm: 1.6; SizeY_mm: 0.8; SizeZ_mm: 1; Value2: 0.1W; SizeArea_mm2: 1.28; AEC Qualified: N; VDC_V: 75V; AEC Category: Q200; SizeAreaWB_mm2: 4.68
R33 = CMP-0023062-5: RES, 37.4 k, 1%, 0.1 W, 0603; Manufacturer: Yageo; Power_W: 100mW; TempCo: 100 ppm/C; Value_Code: 37k4; Value: 37.4k; EIA_Code: E96; SizeX_mm: 1.6; SizeY_mm: 0.8; SizeZ_mm: 1; Value2: 0.1W; SizeArea_mm2: 1.28; AEC Qualified: N; VDC_V: 75V; AEC Category: Q200; SizeAreaWB_mm2: 4.68
R100-R107 = CMP-0018258-2: RES, 3.65 k, 1%, 0.25 W, 1206; Manufacturer: Yageo America; Power_W: 250mW; TempCo: 100 ppm/C; Value_Code: 3k65; U/M: EA; Value: 3.65k; EIA_Code: E96; SizeX_mm: 3.2; SizeY_mm: 1.6; SizeZ_mm: 1.35; Value2: 0.25W; SizeArea_mm2: 5.12; VDC_V: 200V; AEC Category: Q200
R108 = CMP-0022680-4: RES, 1.00 k, 1%, 0.1 W, 0603; Manufacturer: Panasonic; Power_W: 100mW; TempCo: 100 ppm/C; Value_Code: 1k00; U/M: EA; Value: 1.00k; EIA_Code: E96; Res_ohm: 1k; SizeX_mm: 1.6; SizeY_mm: 0.8; SizeZ_mm: 1; SizeArea_mm2: 1.28; VDC_V: 75V; AEC Category: Q200; Value2: 0.1W
T1 = CMP-0120310-1: Backlight LLC Transformer; Manufacturer: Payton Planar; Ind_H: 200µH; Ns1toNp: 10:1+1; SizeZ_mm: 10mm; AEC Qualified: No; Frequency_Fixed: 80-250kHz; TaMax_C: +30°C; TaMin_C: -40°C; Voltage_Isolation_Vrms: 2500VDC
TP1 TP2 = CMP-0055148-2: Test Point, Multipurpose, Black, TH; Manufacturer: Keystone Electronics; CNHeader: FALSE; ContactFinish: Silver; Green_REACh: Passed; Green_Lifecycle: Active; CT: TRUE
TP5 VIN = CMP-0055147-2: Test Point, Multipurpose, Red, TH; Manufacturer: Keystone Electronics; CNHeader: FALSE; Green_Lifecycle: Active; Green_REACh: Passed; ContactFinish: Silver; CT: TRUE
TP6 = CMP-0055150-2: Test Point, Multipurpose, Orange, TH; Manufacturer: Keystone Electronics; CNHeader: FALSE; Green_Lifecycle: Active; Green_REACh: Passed; ContactFinish: Silver; CT: TRUE
TP7 = CMP-0055149-2: Test Point, Multipurpose, White, TH; Manufacturer: Keystone Electronics; CNHeader: FALSE; Green_Lifecycle: Active; Green_REACh: Passed; ContactFinish: Silver; CT: TRUE
TP8 = CMP-0055149-2: Test Point, Multipurpose, White, TH; Manufacturer: Keystone Electronics; ContactFinish: Silver; CT: TRUE; CNHeader: FALSE; Green_Lifecycle: Active; Green_REACh: Passed
U1 U2 = CMP-0013047-3: High-Frequency Multi-Mode Synchronous Rectifier Controller, DBV0005A (SOT-23-5); Manufacturer: Texas Instruments; Alternate PartNumber: UCC24612-2DBVR; SizeX_mm: 2.8; SizeY_mm: 2.9; CompType: IC; SizeZ_mm: 1.45; SizeArea_mm2: 8.12; SizeAreaWB_mm2: 14.82; AEC Category: Q200; AEC Qualified: N
U3 = CMP-0083653-1: Optocoupler, 5.3 kV, 100-200% CTR, SMT; Manufacturer: Vishay-Semiconductor; CTR (Max): 200%; SizeAreaWB_mm2: 71.064; CTR (Min): 100%; SizeZ_mm: 5; SizeX_mm: 8.8; SizeY_mm: 4.58; SizeArea_mm2: 40.304; Voltage_Isolation_Vrms: 5.3kV
U4 = CMP-0095299-1: 750kHz Wide VIN/VOUT Range LLC Controller Optimized for Light Load Efficiency; Manufacturer: Texas Instruments; Number Of Outputs: 2; TaMax_C: +125°C; Output Type: Other; TJmax_C: +150°C; AEC Qualified: No; Standoff Height: 0.1mm; TaMin_C: -40°C; SizeZ_mm: 1.75mm; Switching Frequency: 30-750kHz; Max Supply Voltage: 18.5V
U5 = CMP-0033002-1: Adjustable Precision Shunt Regulator, 34 ppm / degC, 100 mA, -40 to 85 degC, 3-pin SOT-23 (DBZ), Green (RoHS & no Sb/Br); Manufacturer: Texas Instruments; VO Adj(Min)(V): 2.495; Iout/Iz(Max)(mA): 100; Initial Accuracy @ 25/deg C(%): 1; SubFamily: Shunt Voltage Reference; Rating: Catalog; Temp Coeff(Typ)(ppm/ degree C): 34; VO Adj(Max)(V): 36; Temp Coeff(Max)(ppm/ degree C): 92; Min Iz for Regulation(uA): 600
